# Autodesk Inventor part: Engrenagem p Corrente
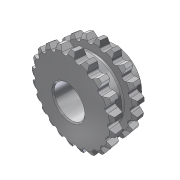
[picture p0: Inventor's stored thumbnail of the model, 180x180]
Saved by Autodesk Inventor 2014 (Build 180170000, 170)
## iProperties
Created: 2013-09
Part Number: Engrenagem p Corrente
Material: Generic
Document SubType Name: Modeling
Designer: User
Density: 1 g/cm^3
Appearance: Polished - Small Pyramid Knurl
Author: User
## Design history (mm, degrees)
sketch "Sketch1"
  geometry: C1 r 34.06 at (0, 0); 1 further point
  constraints: 1 centre point, 1 coincident
  dimensions: "d0" = 68.12 diameter of C1
extrude "Extrusion1" new body sketch "Sketch1" distance "d1" = 7.5; taper "d2" = 0 deg
sketch "Sketch2"
  geometry: C1 r 34.06 at (0, 0) reference; C2 r 25 at (0, 0)
  constraints: 1 centre point, 1 coincident
  dimensions: "d3" = 50 diameter of C2
extrude "Extrusion2" join sketch "Sketch2" distance "d4" = 10; taper "d5" = 0 deg
sketch "Sketch3"
  geometry: C1 r 34.06 at (0, 0) reference
extrude "Extrusion3" join sketch "Sketch3" distance "d6" = 7.5; taper "d7" = 0 deg
sketch "Sketch4"
  geometry: C1 r 25 at (0, 0) reference
extrude "Extrusion4" join sketch "Sketch4" distance "d8" = 10; taper "d9" = 0 deg
chamfer "Chamfer1" distance "d10" = 3; stored, may be unused: second distance "d11" = 1, angle "d12" = 45 deg
chamfer "Chamfer2" distance "d13" = 3; stored, may be unused: second distance "d14" = 1, angle "d15" = 45 deg
chamfer "Chamfer3" distance "d16" = 3; stored, may be unused: second distance "d17" = 1, angle "d18" = 45 deg
chamfer "Chamfer4" distance "d19" = 3; stored, may be unused: second distance "d20" = 1, angle "d21" = 45 deg
sketch "Sketch5"
  geometry: L1 (-4.245, 34.675)-(-1.933, 30.671); L2 (0, 31.787)-(0, 35.874); L3 (4.245, 34.675)-(1.933, 30.671); L4 (-4.245, 34.675)-(4.245, 34.675); C1 r 34.06 at (0, 0) reference; C2 r 31.955 at (0, 0); C3 r 29.555 at (0, 0); A1 r 2.232 centre (0, 31.787) between (-1.933, 30.671) and (1.933, 30.671)
  constraints: 8 end point, 3 centre point, 2 coincident, 2 point on circle, 2 symmetric about line, 2 tangent, 1 perpendicular, 1 point on line, 1 vertical
  dimensions: "d22" = 63.91 diameter of C2; "d23" = 2.4 radial gap between concentric circles of C3 C2; "d24" = 60 deg angle of L3 L1
extrude "Extrusion5" cut sketch "Sketch5" stored distance "d25" = 10; taper "d26" = 0 deg
chamfer "Chamfer5" distance "d30" = 1; stored, may be unused: second distance "d31" = 1, angle "d32" = 45 deg
fillet "Fillet1" dims "d33" = 1
sketch "Sketch6"
  geometry: C1 r 24 at (0, 0) reference; C2 r 12.7 at (0, 0)
  constraints: 1 centre point, 1 coincident
  dimensions: "d34" = 25.4 diameter of C2
extrude "Extrusion6" cut sketch "Sketch6" stored distance "d35" = 10; taper "d36" = 0 deg
chamfer "Chamfer6" distance "d37" = 1; stored, may be unused: second distance "d38" = 1, angle "d39" = 45 deg
body "Solid1"
pattern_circular "Circular Pattern1" dims angle "d28" = 360 deg
